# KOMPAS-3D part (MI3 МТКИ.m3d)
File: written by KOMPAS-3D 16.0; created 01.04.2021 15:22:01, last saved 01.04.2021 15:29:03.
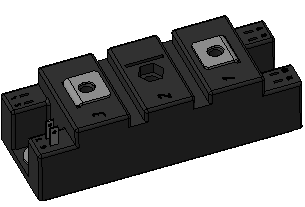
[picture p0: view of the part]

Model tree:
1. Операция без истории:1  (with: Сечение модели:2)

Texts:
  Точка начала. Х
  Точка начала. Y
  Точка начала. Z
